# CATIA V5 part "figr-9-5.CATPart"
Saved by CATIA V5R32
Part number: Part1
Bounding box of the stored display mesh (mm): x -71.324 to 69.61, y -211.059 to 0, z 0 to 45
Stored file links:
  D:\PROJECTS\Project 2022\CATIA V5 6R 2022\Resources\Part Files\c09_catia_v5_6r2022_prt\c09_catia_v5_6r2022_prt\figr-9-5.CATPart
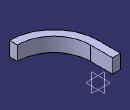
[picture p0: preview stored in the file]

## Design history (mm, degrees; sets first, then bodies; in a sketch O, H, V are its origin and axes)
Body1 (main body)
  Sketch1 on xy-plane, origin (0, 0, 0), H (1, 0, 0), V (0, 1, 0)
    line L1 (0, 0) -> (0, -70.1255)
    arc A1 centre (69.6095, -70.1255) radius 69.6095 from (0, -70.1255) to (69.6095, -139.7351) ccw
    vertical: L1 V
    tangency: A1 L1
  Sketch2 on zx-plane, origin (0, 0, 0), H (-1, 0, 0), V (0, 0, 1)
    point P1 (46.3244, 0)
    line L1 (46.3244, 0) -> (71.3244, 0)
    line L2 (71.3244, 0) -> (71.3244, 45)
    line L3 (71.3244, 45) -> (46.3244, 45)
    line L4 (46.3244, 45) -> (46.3244, 0)
    length L3 = 25
    length L2 = 45
    coincidence: P1 H
    horizontal: L1 H, L3 H
    vertical: L2 V, L4 V
  Rib1: profile Sketch2, centre curve Sketch1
